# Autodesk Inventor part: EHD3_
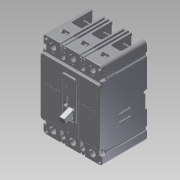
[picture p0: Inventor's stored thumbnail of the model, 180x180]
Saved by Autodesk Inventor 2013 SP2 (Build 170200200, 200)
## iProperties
Created: 2014-08
Part Number: EHD3_
Material: Generic
Document SubType Name: Modeling
Designer: DM/JS
Density: 1 g/cm^3
Description: TYPE EHD THERMAL MAGNETIC CIRCUIT BREAKERS THREE POLE, SERIES C
Translation Standard: STEP AP214IS
FileName: Y:\ECO-062745\WIP\New\FD3_.stp
PreProcessor: Autodesk Inventor 2012
PostProcessor: Build: 219, Release: 2012 SP2 - Date: Fri 04/27/2012
Sent Units: inch
Uncertainty: 0.00039370078740199997
MXEDIT: false
MXINVTNRV: INV Versioned Component|EHD3_|003.0
Author: DM/JS
Revision Number: 003
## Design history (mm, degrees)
node "EHD3_"
node "L1"
node "L2"
node "L3"
node "T1"
node "T2"
node "T3"
body "Solid1"
node "Base1"
